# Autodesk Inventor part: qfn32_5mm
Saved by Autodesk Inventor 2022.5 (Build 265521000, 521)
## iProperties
Created: 2024-12
Part Number: qfn32_5mm
Material: Generic
Document SubType Name: Modeling
Designer: AdminForWorker
Density: 1 g/cm^3
Appearance: Default
Title: qfn32_5mm v1
Author: AdminForWorker
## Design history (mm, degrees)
feature "Body1"
feature "Body64"
feature "Body67"
feature "Body68"
feature "Body69"
feature "Body70"
feature "Body71"
feature "Body72"
feature "Body73"
feature "Body100"
feature "Body101"
feature "Body102"
feature "Body91"
feature "Body92"
feature "Body93"
feature "Body88"
feature "Body89"
feature "Body90"
feature "Body97"
feature "Body98"
feature "Body99"
feature "Body85"
feature "Body86"
feature "Body87"
feature "Body94"
feature "Body95"
feature "Body96"
feature "Body82"
feature "Body83"
feature "Body84"
feature "Body106"
feature "Body107"
feature "Body108"
body "Solid1"
body "Solid2"
body "Solid3"
body "Solid4"
body "Solid5"
body "Solid6"
body "Solid7"
body "Solid8"
body "Solid9"
body "Solid10"
body "Solid11"
body "Solid12"
body "Solid13"
body "Solid14"
body "Solid15"
body "Solid16"
body "Solid17"
body "Solid18"
body "Solid19"
body "Solid20"
body "Solid21"
body "Solid22"
body "Solid23"
body "Solid24"
body "Solid25"
body "Solid26"
body "Solid27"
body "Solid28"
body "Solid29"
body "Solid30"
body "Solid31"
body "Solid32"
body "Solid33"
